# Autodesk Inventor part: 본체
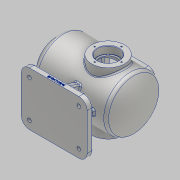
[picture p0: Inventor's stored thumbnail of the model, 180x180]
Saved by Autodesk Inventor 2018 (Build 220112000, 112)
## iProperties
Created: 2021-11
Part Number: 본체
Material: 알루미늄 6061
Document SubType Name: Modeling
Designer: home
Density: 2.7 g/cm^3
Appearance: 알루미늄 - 평지
Mass: 3539.14 g
Surface Area: 2407.21 cm^2
Volume: 1310.79 cm^3
Author: home
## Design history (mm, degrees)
sketch "스케치1"
  geometry: L1 (80, 65)-(-80, 65); L2 (-80, 65)-(-80, -65); L3 (-80, -65)-(80, -65); L4 (80, -65)-(80, 65); L5 (80, 65)-(-80, -65); L6 (-80, 65)-(80, -65); 1 further point
  constraints: 12 end point, 2 midpoint, 2 parallel, 1 horizontal, 1 perpendicular
  dimensions: "d0" = 160 distance of L2.end L3.end; "d1" = 130 distance of L1.end L2.end
extrude "돌출1" new body sketch "스케치1" distance "d2" = 14; taper "d3" = 0 deg
fillet "모깎기1" dims "d4" = 20
sketch "스케치2"
  geometry: L1 (-103.289, 114)-(100, 114); L2 (60, 0)-(-60, 0) reference; L3 (-110, 146.5)-(-85, 146.5); L4 (-85, 146.5)-(-85, 169); L5 (-85, 169)-(71.239, 169); L6 (-110, 146.5)-(-110, 161.5); L7 (-110, 161.5)-(-100, 161.5); L8 (-100, 161.5)-(-100, 179); L9 (-100, 179)-(75.993, 179); L10 (-80, 0)-(-80, 14) reference; A1 r 100 centre (0, 114) between (100, 114) and (75.993, 179); A2 r 90 centre (0, 114) between (90, 114) and (71.239, 169); 1 further point
  constraints: 16 end point, 5 perpendicular, 4 point on circle, 2 centre point, 2 horizontal, 1 point on line, 1 vertical
  dimensions: "d5" = 114 distance between parallel lines of L2 L1; "d6" = 65 diameter of L3 L1; "d7" = 95 diameter of L7 L1; "d8" = 110 diameter of L5 L1; "d9" = 130 diameter of L9 L1; "d15" = 10 radial gap between concentric circles of A1 A2; "d16" = 10 distance of L6.end L7.end; "d17" = 100 radius of A1; "d18" = 25 distance of L3.start L3.end; "d20" = 110 distance from line of L6 A1.centre; "d22" = 30 distance between parallel lines of L10 L6; "d23" = 55 distance from line of L5 A1.centre
revolve "회전1" sketch "스케치2" stored, may be unused: angle "d24" = 90 deg
sketch "스케치3"
  geometry: L1 (60, 14)-(-60, 14) reference; L2 (-60, 14)-(-45.352, 54.246); L3 (60, 14)-(45.352, 54.246); L4 (-100, 49)-(75.993, 49) reference; L5 (-60, 14)-(60, 14); L6 (-80, 14)-(-60, 14) reference; L7 (60, 14)-(80, 14) reference; L8 (-45.352, 54.246)-(45.352, 54.246); L9 (71.239, 59)-(-85, 59) reference; 2 further points
  constraints: 8 end point, 2 point on line, 1 collinear, 1 parallel, 1 vertical alignment
  dimensions: "d25" = 120 distance of L3.start L2.start; "d26" = 110 deg angle of L6 L2; "d27" = 110 deg angle of L7 L3; "d28" = 90.70367 distance of L2.end L3.end; "d29" = 61.16984 distance from line of L2 point (0, 0)
extrude "돌출2" join sketch "스케치3" stored distance "d30" = 14; taper "d31" = 0 deg
sketch "스케치4"
  geometry: L1 (14, -45)-(14, -65) reference; L2 (14, -50)-(58.485, -33.809); 2 further points
  constraints: 2 end point, 1 point on line, 2 other
  dimensions: "d32" = 50 vertical distance of point (0, 0) L2.start; "d33" = 110 deg angle of L1 L2
feature "리브1" sketch "스케치4" dims "d34" = 1, "d35" = 14, "d36" = 0, "d37" = 0, "d38" = 1, "d39" = 1
node "작업 평면1"
node "작업 평면2"
sketch "스케치8"
  geometry: L1 (60, 30)-(-60, 30); L2 (-60, 30)-(-60, -30); L3 (-60, -30)-(60, -30); L4 (60, -30)-(60, 30); L5 (110, 47.5)-(110, -47.5) reference; L6 (60, 0)-(-60, 0); 2 further points
  constraints: 10 end point, 3 midpoint, 2 parallel, 1 coincident, 1 horizontal, 1 perpendicular
  dimensions: "d53" = 50 distance between parallel lines of L4 L5; "d54" = 120 distance between parallel lines of L2 L4; "d55" = 60 distance between parallel lines of L1 L3
extrude "돌출5" join sketch "스케치8" stored distance "d56" = 18; taper "d57" = 0 deg
sketch "스케치9"
  geometry: L1 (-50, -20)-(50, -20); L2 (50, -20)-(50, 20); L3 (50, 20)-(-50, 20); L4 (-50, 20)-(-50, -20); L5 (-50, 0)-(50, 0); L6 (-60, 30)-(-60, -30) reference; L7 (60, -30)-(60, 30) reference; L8 (60, 30)-(-60, 30) reference; L9 (-60, -30)-(60, -30) reference; 1 further point
  constraints: 10 end point, 2 midpoint, 2 parallel, 1 horizontal, 1 perpendicular
  dimensions: "d58" = 10 distance between parallel lines of L6 L4; "d59" = 10 distance between parallel lines of L7 L2; "d60" = 10 distance between parallel lines of L8 L3; "d61" = 10 distance between parallel lines of L9 L1
extrude "돌출6" cut sketch "스케치9" stored distance "d62" = 18; taper "d63" = 0 deg
fillet "모깎기2" dims "d64" = 15
fillet "모깎기3" dims "d65" = 5
fillet "모깎기4" dims "d66" = 10
fillet "모깎기5" dims "d67" = 3
fillet "모깎기6" dims "d68" = 3
fillet "모깎기7" dims "d69" = 3
chamfer "모따기1" distance "d70" = 1; stored, may be unused: second distance "d71" = 2, angle "d72" = 45 deg
fillet "모깎기9" dims "d74" = 3
sketch "스케치10"
  geometry: L1 (60, 65)-(-60, 65) reference; L2 (80, -45)-(80, 45) reference; L3 (-60, -65)-(60, -65) reference; L4 (-80, 45)-(-80, -45) reference; A1 r 20 centre (60, 45) between (80, 45) and (60, 65) reference; A2 r 20 centre (60, 45) between (80, 45) and (60, 65) reference; A3 r 20 centre (60, -45) between (60, -65) and (80, -45) reference; A4 r 20 centre (-60, -45) between (-80, -45) and (-60, -65) reference; A5 r 20 centre (-60, 45) between (-60, 65) and (-80, 45) reference; 1 further point
hole "구멍1" sketch "스케치10" at (-60, 45), (-60, -45), (60, 45), (60, -45) diameter "d75" = 9; stored, may be unused: countersink angle "d79" = 90 deg, drill point angle "d81" = 0 deg; dims "d76" = 6, "d77" = 18, "d78" = 2, "d80" = 8
sketch "스케치11"
  geometry: C1 r 47.5 at (0, 0) reference; 2 further points
  constraints: 1 vertical alignment
  dimensions: "d82" = 40 distance of C1.centre point (0, 40)
hole "구멍2" sketch "스케치11" at (0, 40) diameter "d83" = 3.242; stored, may be unused: countersink angle "d87" = 90 deg, drill point angle "d89" = 118 deg; dims "d84" = 11, "d85" = 18, "d86" = 2, "d88" = 13
sketch "스케치13"
  geometry: L1 (50, 15)-(50, -15) reference; L2 (45, -20)-(-45, -20) reference; L3 (-50, -15)-(-50, 15) reference; L4 (-45, 20)-(45, 20) reference; L5 (45, 30)-(-45, 30) reference; L6 (-60, 15)-(-60, -15) reference; L7 (-45, -30)-(45, -30) reference; L8 (60, -15)-(60, 15) reference; A1 r 5 centre (45, -15) between (45, -20) and (50, -15) reference; A2 r 5 centre (-45, -15) between (-50, -15) and (-45, -20) reference; A3 r 5 centre (-45, 15) between (-45, 20) and (-50, 15) reference; A4 r 5 centre (45, 15) between (50, 15) and (45, 20) reference; A5 r 15 centre (45, 15) between (60, 15) and (45, 30) reference; A6 r 15 centre (-45, 15) between (-45, 30) and (-60, 15) reference; A7 r 15 centre (-45, -15) between (-60, -15) and (-45, -30) reference; A8 r 15 centre (45, -15) between (45, -30) and (60, -15) reference; 6 further points
  constraints: 2 horizontal alignment, 2 vertical alignment, 1 midpoint
  dimensions: "d104" = 55 distance of point (0, 0) point (-55, 0); "d105" = 55 distance of point (0, 0) point (55, 0); "d106" = 50 distance of point (0, -25) point (0, 25); "d107" = 25 distance of point (0, 0) point (0, 25)
hole "구멍4" sketch "스케치13" at (0, 25), (0, -25), (-55, 0), (55, 0) diameter "d108" = 3.242; stored, may be unused: countersink angle "d112" = 90 deg, drill point angle "d114" = 118 deg; dims "d109" = 9, "d110" = 18, "d111" = 2, "d113" = 11
node "작업 평면3"
sketch "스케치14"
  geometry: L1 (-45.822, 8.766)-(45.822, 8.766); L2 (45.822, 8.766)-(45.822, 1.234); L3 (45.822, 1.234)-(-45.822, 1.234); L4 (-45.822, 1.234)-(-45.822, 8.766); L5 (-45.822, 5)-(45.822, 5); L6 (0, 8.766)-(0, 1.234); L7 (-60, 0)-(60, 0) reference; 2 further points
  constraints: 5 midpoint, 4 end point, 1 vertical alignment, 2 other
  dimensions: "d147" = 5 distance between parallel lines of L7 L5
feature "엠보싱1" sketch "스케치14" dims "d5" = 114, "d6" = 65, "d7" = 95, "d8" = 110, "d9" = 130, "d15" = 10, "d16" = 10, "d17" = 100, "d18" = 25, "d20" = 110, "d22" = 30, "d23" = 55, "d116" = 0.5, "d117" = 0
node "작업 평면4"
sketch "스케치15"
  geometry: L1 (-110, 66.5)-(-110, 161.5) reference; C1 r 40 at (17, 114); 2 further points
  constraints: 1 centre point, 1 horizontal alignment, 1 midpoint
  dimensions: "d121" = 127 distance from line of L1 C1.centre; "d122" = 80 diameter of C1
extrude "돌출7" join sketch "스케치15" stored distance "d123" = 40; taper "d124" = 0 deg
sketch "스케치16"
  geometry: C1 r 40 at (0, 0) reference; C2 r 26 at (0, 0); 1 further point
  constraints: 1 centre point, 1 coincident
  dimensions: "d125" = 52 diameter of C2
extrude "돌출8" cut sketch "스케치16" distance "d126" = 18; taper "d127" = 0 deg
sketch "스케치17"
  geometry: C1 r 26 at (0, 0) reference; C2 r 21 at (0, 0); 1 further point
  constraints: 1 centre point, 1 coincident
  dimensions: "d128" = 42 diameter of C2
extrude "돌출9" cut sketch "스케치17" stored distance "d129" = 18; taper "d130" = 0 deg
sketch "스케치18"
  geometry: C1 r 40 at (0, 0) reference; 2 further points
  constraints: 1 vertical alignment
  dimensions: "d131" = 32.5 distance of C1.centre point (0, 32.5)
hole "구멍5" sketch "스케치18" at (0, 32.5) diameter "d132" = 3.242; stored, may be unused: countersink angle "d136" = 90 deg, drill point angle "d138" = 118 deg; dims "d133" = 11, "d134" = 18, "d135" = 2, "d137" = 13
fillet "모깎기10" dims "d142" = 3
chamfer "모따기2" distance "d143" = 1; stored, may be unused: second distance "d144" = 2, angle "d145" = 45 deg
fillet "모깎기11" dims "d146" = 0.3
node "솔리드1"
mirror "미러1"
pattern_circular "원형 패턴1" dims angle "d91" = 360 deg
pattern_circular "원형 패턴3" dims angle "d140" = 360 deg
mirror "미러5"
node "투영된 루프1"
node "투영된 루프2"
other parameters: "d40" = -127, "d52" = 184, "d115" = 126.25, "d120" = 75
